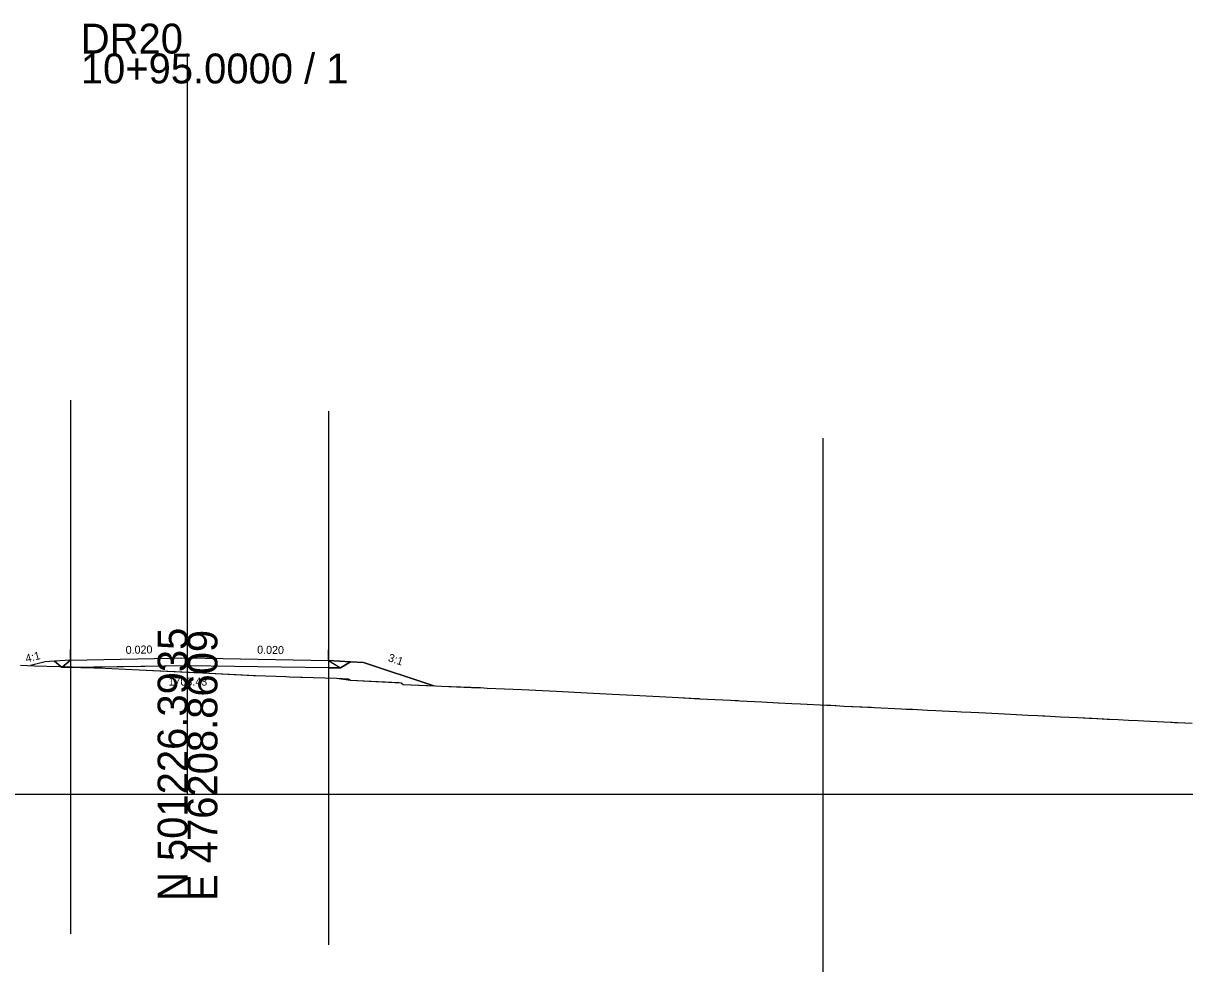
# Model space of a CAD drawing. Extents: x 78027 to 79855, y -93601 to -93005.
# Drawn here: x 78237.1 to 78345.9, y -93093.8 to -93005 of the extents above; entities that cross this region are included whole.
import ezdxf

# ---------------------------------------------------------------- set-up
doc = ezdxf.new("R2010")
doc.units = 0
for name, color, linetype in [('Exist Cross Section Cell', 7, 'Continuous'), ('Exist XS Center Line Elevation Label', 7, 'Continuous'), ('Exist XS Ground Line', 7, 'Continuous'), ('Prop XS Earthwork Shape', 7, 'Continuous'), ('Prop XS EOT Tick Mark', 7, 'Continuous'), ('Prop XS Finish Grade', 7, 'Continuous'), ('Prop XS Finish Grade Earthwork', 7, 'Continuous'), ('Prop XS Finish Grade Pavement', 7, 'Continuous'), ('Prop XS Pvmt Edge Slope', 7, 'Continuous'), ('Prop XS SE Text', 7, 'Continuous'), ('Prop XS Shoulder Borrow Shape', 7, 'Continuous'), ('Prop XS Side Slope Text', 7, 'Continuous'), ('Prop XS Subgrade Earthwork', 7, 'Continuous'), ('Scratch_Level_0', 7, 'Continuous'), ('Scratch_Level_4', 7, 'Continuous'), ('Scratch_Level_5', 7, 'Continuous'), ('Scratch_Level_6', 7, 'Continuous')]:
    doc.layers.add(name, color=color, linetype=linetype)

msp = doc.modelspace()

# ---------------------------------------------------------------- linework, layer by layer
at = {"layer": 'Exist Cross Section Cell'}
for p, q in [((78252.48, -93077.22), (78252.48, -93007.82)), ((78052.48, -93077.22), (78252.48, -93077.22)), ((78252.48, -93077.22), (78452.48, -93077.22))]:
    msp.add_line(p, q, dxfattribs=at)
at = {"layer": 'Exist XS Ground Line'}
for p, q in [((78236.82, -93065.11), (78238.15, -93065.18)), ((78238.15, -93065.18), (78240.47, -93065.26)), ((78240.47, -93065.26), (78240.99, -93065.26)), ((78240.99, -93065.26), (78243.76, -93065.38)), ((78243.76, -93065.38), (78244.11, -93065.38)), ((78244.11, -93065.38), (78247.95, -93065.56)), ((78247.95, -93065.56), (78252.48, -93065.79)), ((78252.48, -93065.79), (78252.58, -93065.79)), ((78252.58, -93065.79), (78252.65, -93065.79)), ((78252.65, -93065.79), (78253.09, -93065.8)), ((78253.09, -93065.8), (78253.28, -93065.81)), ((78253.28, -93065.81), (78258.65, -93066.08)), ((78258.65, -93066.08), (78258.69, -93066.08)), ((78258.69, -93066.08), (78258.86, -93066.09)), ((78258.86, -93066.09), (78261.69, -93066.19)), ((78261.69, -93066.19), (78262.39, -93066.24)), ((78262.39, -93066.24), (78262.75, -93066.23)), ((78262.75, -93066.23), (78263.08, -93066.24)), ((78263.08, -93066.24), (78263.27, -93066.25)), ((78263.27, -93066.25), (78264.27, -93066.29)), ((78264.27, -93066.29), (78266.45, -93066.35)), ((78266.45, -93066.35), (78267.56, -93066.41)), ((78267.56, -93066.41), (78267.76, -93066.52)), ((78267.76, -93066.52), (78272.27, -93066.76)), ((78272.27, -93066.76), (78272.5, -93066.77)), ((78272.5, -93066.77), (78272.68, -93066.93)), ((78272.68, -93066.93), (78275.72, -93067.06)), ((78275.72, -93067.06), (78276.27, -93067.09)), ((78276.27, -93067.09), (78279.78, -93067.24)), ((78279.78, -93067.24), (78279.95, -93067.21)), ((78279.95, -93067.21), (78280.57, -93067.27)), ((78280.57, -93067.27), (78283.82, -93067.41)), ((78283.82, -93067.41), (78287.07, -93067.56)), ((78287.07, -93067.56), (78288.74, -93067.64)), ((78288.74, -93067.64), (78292.31, -93067.83)), ((78292.31, -93067.83), (78292.97, -93067.86)), ((78292.97, -93067.86), (78293.61, -93067.9)), ((78293.61, -93067.9), (78296.71, -93068.06)), ((78296.71, -93068.06), (78298.5, -93068.16)), ((78298.5, -93068.16), (78300.25, -93068.25)), ((78300.25, -93068.25), (78300.42, -93068.26)), ((78300.42, -93068.26), (78300.49, -93068.27)), ((78300.49, -93068.27), (78303.38, -93068.41)), ((78303.38, -93068.41), (78304.01, -93068.44)), ((78304.01, -93068.44), (78304.05, -93068.44)), ((78304.05, -93068.44), (78304.07, -93068.44)), ((78304.07, -93068.44), (78304.25, -93068.45)), ((78304.25, -93068.45), (78306.29, -93068.56)), ((78306.29, -93068.56), (78307.83, -93068.64)), ((78307.83, -93068.64), (78309.1, -93068.7)), ((78309.1, -93068.7), (78309.92, -93068.74)), ((78309.92, -93068.74), (78312.39, -93068.87)), ((78312.39, -93068.87), (78312.76, -93068.88)), ((78312.76, -93068.88), (78313.18, -93068.91)), ((78313.18, -93068.91), (78313.23, -93068.91)), ((78313.23, -93068.91), (78314, -93068.95)), ((78314, -93068.95), (78316.25, -93069.06)), ((78316.25, -93069.06), (78316.54, -93069.07)), ((78316.54, -93069.07), (78316.86, -93069.09)), ((78316.86, -93069.09), (78319.39, -93069.21)), ((78319.39, -93069.21), (78319.82, -93069.23)), ((78319.82, -93069.23), (78320.41, -93069.26)), ((78320.41, -93069.26), (78321.83, -93069.33)), ((78321.83, -93069.33), (78322.61, -93069.37)), ((78322.61, -93069.37), (78323.19, -93069.4)), ((78323.19, -93069.4), (78324.57, -93069.47)), ((78324.57, -93069.47), (78325, -93069.49)), ((78325, -93069.49), (78325.9, -93069.54)), ((78325.9, -93069.54), (78326.65, -93069.57)), ((78326.65, -93069.57), (78328.48, -93069.66)), ((78328.48, -93069.66), (78329.05, -93069.69)), ((78329.05, -93069.69), (78329.6, -93069.72)), ((78329.6, -93069.72), (78331.22, -93069.8)), ((78331.22, -93069.8), (78332.17, -93069.85)), ((78332.17, -93069.85), (78332.65, -93069.87)), ((78332.65, -93069.87), (78332.81, -93069.88)), ((78332.81, -93069.88), (78334.3, -93069.95)), ((78334.3, -93069.95), (78335.9, -93070.03)), ((78335.9, -93070.03), (78336.99, -93070.08)), ((78336.99, -93070.08), (78337.23, -93070.1)), ((78337.23, -93070.1), (78338.68, -93070.17)), ((78338.68, -93070.17), (78338.91, -93070.18)), ((78338.91, -93070.18), (78339.7, -93070.22)), ((78339.7, -93070.22), (78340.65, -93070.27)), ((78340.65, -93070.27), (78341.58, -93070.32)), ((78341.58, -93070.32), (78342.09, -93070.34)), ((78342.09, -93070.34), (78343.99, -93070.43)), ((78343.99, -93070.43), (78344.77, -93070.47)), ((78344.77, -93070.47), (78344.98, -93070.48)), ((78344.98, -93070.48), (78345.25, -93070.49)), ((78345.25, -93070.49), (78346.62, -93070.56))]:
    msp.add_line(p, q, dxfattribs=at)
at = {"layer": 'Prop XS Earthwork Shape'}
for points in [[(78240.61, -93065.26), (78240.01, -93064.75), (78239.14, -93064.81), (78237.76, -93065.16), (78238.15, -93065.18), (78240.47, -93065.26)], [(78240.61, -93065.26), (78240.01, -93064.75), (78239.14, -93064.81), (78237.76, -93065.16), (78238.15, -93065.18), (78240.47, -93065.26)], [(78242.49, -93065.33), (78243.76, -93065.38), (78244.11, -93065.38), (78247.95, -93065.56), (78252.48, -93065.79), (78252.58, -93065.79), (78252.65, -93065.79), (78253.09, -93065.8), (78253.28, -93065.81), (78258.65, -93066.08), (78258.69, -93066.08), (78258.86, -93066.09), (78261.69, -93066.19), (78262.39, -93066.24), (78262.75, -93066.23), (78263.08, -93066.24), (78263.27, -93066.25), (78264.27, -93066.29), (78266.45, -93066.35), (78267.56, -93066.41), (78267.76, -93066.52), (78272.27, -93066.76), (78272.5, -93066.77), (78272.68, -93066.93), (78275.56, -93067.06), (78268.97, -93064.86), (78267.76, -93064.8), (78266.81, -93065.38), (78265.7, -93065.36), (78252.48, -93065.2)], [(78242.49, -93065.33), (78243.76, -93065.38), (78244.11, -93065.38), (78247.95, -93065.56), (78252.48, -93065.79), (78252.58, -93065.79), (78252.65, -93065.79), (78253.09, -93065.8), (78253.28, -93065.81), (78258.65, -93066.08), (78258.69, -93066.08), (78258.86, -93066.09), (78261.69, -93066.19), (78262.39, -93066.24), (78262.75, -93066.23), (78263.08, -93066.24), (78263.27, -93066.25), (78264.27, -93066.29), (78266.45, -93066.35), (78267.56, -93066.41), (78267.76, -93066.52), (78272.27, -93066.76), (78272.5, -93066.77), (78272.68, -93066.93), (78275.56, -93067.06), (78268.97, -93064.86), (78267.76, -93064.8), (78266.81, -93065.38), (78265.7, -93065.36), (78252.48, -93065.2)], [(78242.49, -93065.33), (78241.5, -93065.34), (78240.7, -93065.33), (78240.61, -93065.26), (78240.99, -93065.26)], [(78240.61, -93065.26), (78240.99, -93065.26), (78242.49, -93065.33), (78241.5, -93065.34), (78240.7, -93065.33)]]:
    msp.add_lwpolyline(points, close=True, dxfattribs=at)
at = {"layer": 'Prop XS EOT Tick Mark'}
for p, q in [((78241.5, -93064.65), (78241.5, -93063.65)), ((78265.7, -93064.7), (78265.7, -93063.7))]:
    msp.add_line(p, q, dxfattribs=at)
at = {"layer": 'Prop XS Finish Grade'}
for p, q in [((78241.5, -93064.65), (78240.01, -93064.75)), ((78265.7, -93064.7), (78267.76, -93064.8))]:
    msp.add_line(p, q, dxfattribs=at)
at = {"layer": 'Prop XS Finish Grade Earthwork'}
for p, q in [((78239.14, -93064.81), (78237.76, -93065.16)), ((78240.01, -93064.75), (78239.14, -93064.81)), ((78267.76, -93064.8), (78268.97, -93064.86)), ((78268.97, -93064.86), (78275.56, -93067.05))]:
    msp.add_line(p, q, dxfattribs=at)
at = {"layer": 'Prop XS Finish Grade Pavement'}
for p, q in [((78241.5, -93064.65), (78252.48, -93064.43)), ((78252.48, -93064.43), (78265.7, -93064.7))]:
    msp.add_line(p, q, dxfattribs=at)
at = {"layer": 'Prop XS Pvmt Edge Slope'}
for p, q in [((78241.5, -93064.65), (78240.7, -93065.33)), ((78265.7, -93064.7), (78266.81, -93065.38))]:
    msp.add_line(p, q, dxfattribs=at)
at = {"layer": 'Prop XS Shoulder Borrow Shape'}
for points in [[(78241.5, -93064.65), (78240.01, -93064.75), (78240.61, -93065.26), (78240.78, -93065.26)], [(78266.81, -93065.38), (78267.76, -93064.8), (78265.7, -93064.7)], [(78240.7, -93065.33), (78240.61, -93065.26), (78240.78, -93065.26)], [(78241.5, -93065.34), (78240.7, -93065.33), (78240.78, -93065.26), (78240.99, -93065.26), (78242.49, -93065.33)]]:
    msp.add_lwpolyline(points, close=True, dxfattribs=at)
at = {"layer": 'Prop XS Subgrade Earthwork'}
for p, q in [((78240.7, -93065.33), (78240.01, -93064.75)), ((78252.48, -93065.2), (78241.5, -93065.34)), ((78265.7, -93065.36), (78252.48, -93065.2)), ((78266.81, -93065.38), (78267.76, -93064.8)), ((78241.5, -93065.34), (78240.7, -93065.33)), ((78265.7, -93065.36), (78266.81, -93065.38))]:
    msp.add_line(p, q, dxfattribs=at)
at = {"layer": 'Scratch_Level_0'}
msp.add_lwpolyline([(78236.82, -93065.11), (78238.15, -93065.18), (78240.47, -93065.26), (78240.99, -93065.26), (78243.76, -93065.38), (78244.11, -93065.38), (78247.95, -93065.56), (78252.65, -93065.79), (78253.28, -93065.81), (78258.86, -93066.09), (78261.69, -93066.19), (78262.39, -93066.24), (78262.75, -93066.23), (78263.27, -93066.25), (78264.27, -93066.29), (78266.45, -93066.35), (78267.76, -93066.52), (78272.5, -93066.77), (78272.68, -93066.93), (78275.72, -93067.06), (78276.27, -93067.09), (78279.95, -93067.21), (78280.57, -93067.27), (78283.82, -93067.41), (78287.07, -93067.56), (78288.74, -93067.64), (78292.31, -93067.83), (78292.97, -93067.86), (78293.61, -93067.9), (78296.71, -93068.06), (78298.5, -93068.16), (78300.49, -93068.27), (78303.38, -93068.41), (78304.25, -93068.45), (78306.29, -93068.56), (78307.83, -93068.64), (78309.1, -93068.7), (78309.92, -93068.74), (78312.39, -93068.87), (78312.76, -93068.88), (78313.23, -93068.91), (78314, -93068.95), (78316.54, -93069.07), (78316.86, -93069.09), (78319.39, -93069.21), (78319.82, -93069.23), (78320.41, -93069.26), (78321.83, -93069.33), (78322.61, -93069.37), (78323.19, -93069.4), (78324.57, -93069.47), (78325, -93069.49), (78325.9, -93069.54), (78326.65, -93069.57), (78328.48, -93069.66), (78329.05, -93069.69), (78329.6, -93069.72), (78331.22, -93069.8), (78332.17, -93069.85), (78332.81, -93069.88), (78334.3, -93069.95), (78335.9, -93070.03), (78337.23, -93070.1), (78338.91, -93070.18), (78339.7, -93070.22), (78340.65, -93070.27), (78341.58, -93070.32), (78342.09, -93070.34), (78343.99, -93070.43), (78345.25, -93070.49), (78346.62, -93070.56)], dxfattribs=at)
at = {"layer": 'Scratch_Level_4'}
for p, q in [((78241.5, -93040.28), (78241.5, -93090.28)), ((78265.7, -93041.33), (78265.7, -93091.33)), ((78312.03, -93043.85), (78312.03, -93093.85))]:
    msp.add_line(p, q, dxfattribs=at)
at = {"layer": 'Scratch_Level_5'}
msp.add_lwpolyline([(78236.82, -93065.11), (78238.15, -93065.18), (78240.47, -93065.26), (78240.99, -93065.26), (78243.76, -93065.38), (78244.11, -93065.38), (78247.95, -93065.56), (78252.65, -93065.79), (78253.28, -93065.81), (78258.86, -93066.09), (78261.69, -93066.19), (78262.39, -93066.24), (78262.75, -93066.23), (78263.27, -93066.25), (78264.27, -93066.29), (78266.45, -93066.35), (78267.76, -93066.52), (78272.5, -93066.77), (78272.68, -93066.93), (78275.72, -93067.06), (78276.27, -93067.09), (78279.95, -93067.21), (78280.57, -93067.27), (78283.82, -93067.41), (78287.07, -93067.56), (78288.74, -93067.64), (78292.31, -93067.83), (78292.97, -93067.86), (78293.61, -93067.9), (78296.71, -93068.06), (78298.5, -93068.16), (78300.49, -93068.27), (78303.38, -93068.41), (78304.25, -93068.45), (78306.29, -93068.56), (78307.83, -93068.64), (78309.1, -93068.7), (78309.92, -93068.74), (78312.39, -93068.87), (78312.76, -93068.88), (78313.23, -93068.91), (78314, -93068.95), (78316.54, -93069.07), (78316.86, -93069.09), (78319.39, -93069.21), (78319.82, -93069.23), (78320.41, -93069.26), (78321.83, -93069.33), (78322.61, -93069.37), (78323.19, -93069.4), (78324.57, -93069.47), (78325, -93069.49), (78325.9, -93069.54), (78326.65, -93069.57), (78328.48, -93069.66), (78329.05, -93069.69), (78329.6, -93069.72), (78331.22, -93069.8), (78332.17, -93069.85), (78332.81, -93069.88), (78334.3, -93069.95), (78335.9, -93070.03), (78337.23, -93070.1), (78338.91, -93070.18), (78339.7, -93070.22), (78340.65, -93070.27), (78341.58, -93070.32), (78342.09, -93070.34), (78343.99, -93070.43), (78345.25, -93070.49), (78346.62, -93070.56)], dxfattribs=at)
at = {"layer": 'Scratch_Level_6'}
msp.add_lwpolyline([(78236.82, -93065.11), (78238.15, -93065.18), (78240.47, -93065.26), (78240.99, -93065.26), (78243.76, -93065.38), (78244.11, -93065.38), (78247.95, -93065.56), (78252.65, -93065.79), (78253.28, -93065.81), (78258.86, -93066.09), (78261.69, -93066.19), (78262.39, -93066.24), (78262.75, -93066.23), (78263.27, -93066.25), (78264.27, -93066.29), (78266.45, -93066.35), (78267.76, -93066.52), (78272.5, -93066.77), (78272.68, -93066.93), (78275.72, -93067.06), (78276.27, -93067.09), (78279.95, -93067.21), (78280.57, -93067.27), (78283.82, -93067.41), (78287.07, -93067.56), (78288.74, -93067.64), (78292.31, -93067.83), (78292.97, -93067.86), (78293.61, -93067.9), (78296.71, -93068.06), (78298.5, -93068.16), (78300.49, -93068.27), (78303.38, -93068.41), (78304.25, -93068.45), (78306.29, -93068.56), (78307.83, -93068.64), (78309.1, -93068.7), (78309.92, -93068.74), (78312.39, -93068.87), (78312.76, -93068.88), (78313.23, -93068.91), (78314, -93068.95), (78316.54, -93069.07), (78316.86, -93069.09), (78319.39, -93069.21), (78319.82, -93069.23), (78320.41, -93069.26), (78321.83, -93069.33), (78322.61, -93069.37), (78323.19, -93069.4), (78324.57, -93069.47), (78325, -93069.49), (78325.9, -93069.54), (78326.65, -93069.57), (78328.48, -93069.66), (78329.05, -93069.69), (78329.6, -93069.72), (78331.22, -93069.8), (78332.17, -93069.85), (78332.81, -93069.88), (78334.3, -93069.95), (78335.9, -93070.03), (78337.23, -93070.1), (78338.91, -93070.18), (78339.7, -93070.22), (78340.65, -93070.27), (78341.58, -93070.32), (78342.09, -93070.34), (78343.99, -93070.43), (78345.25, -93070.49), (78346.62, -93070.56)], dxfattribs=at)

# ---------------------------------------------------------------- texts
at = {"layer": 'Exist Cross Section Cell'}
for s, p in [('DR20', (78242.48, -93007.82)), ('10+95.0000 / 1', (78242.48, -93010.62))]:
    msp.add_text(s, height=2.8, dxfattribs=at).set_placement(p)
for s, p in [('N 501226.3935', (78252.48, -93087.22)), ('E 476208.8609', (78255.28, -93087.22))]:
    msp.add_text(s, height=2.8, rotation=90, dxfattribs=at).set_placement(p)
at = {"layer": 'Exist XS Center Line Elevation Label'}
msp.add_text('1703.43', height=0.75, dxfattribs=at).set_placement((78250.7, -93067.04))
at = {"layer": 'Prop XS SE Text'}
for rotation, p in [(1.1458, (78246.69, -93064.07)), (358.8542, (78259, -93064.04))]:
    msp.add_text('0.020', height=0.75, rotation=rotation, dxfattribs=at).set_placement(p)
at = {"layer": 'Prop XS Side Slope Text'}
for s, rotation, p in [('4:1', 14.0362, (78237.39, -93064.88)), ('3:1', 341.5651, (78271.22, -93064.73))]:
    msp.add_text(s, height=0.75, rotation=rotation, dxfattribs=at).set_placement(p)

doc.saveas('drawing.dxf')
